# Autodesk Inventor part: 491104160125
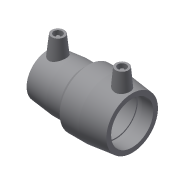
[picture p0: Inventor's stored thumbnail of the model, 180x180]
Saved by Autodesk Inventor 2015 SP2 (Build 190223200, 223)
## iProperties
Created: 2017-06
Part Number: 491104160125
Material: Generic
Description: PLASSON REDUCING COUPLER 160-125
Document SubType Name: Modeling
Designer: KIM
Mass: 54.8237 g
Surface Area: 155.252 cm^2
Volume: 54.8237 cm^3
Density: 1 g/cm^3
Appearance: Default
Author: KIM
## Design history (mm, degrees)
derived "491104.ipt"
feature "Solid1::491104.ipt"
tag "TaggingFeature1"
body "Solid1"
other parameters: "d0" = 195, "d2" = 158, "d3" = 85, "d4" = 51, "d5" = 142.2, "d7" = 125, "d8" = 168 deg, "d10" = 34, "d11" = 11.33333, "d13" = 195, "d14" = 17.6296, "d15" = 85, "d18" = 125, "d19" = 4.25, "d20" = 168 deg, "d22" = 108.92847, "d25" = 135 deg, "d29" = 89, "d30" = 15, "d31" = 68.25, "d34" = 6 deg, "d35" = 15, "d38" = 20.25, "d39" = 5 deg, "d41" = 4, "d42" = 14, "d43" = 0, "d45" = 4, "d46" = 14, "d47" = 0, "d48" = 158, "d50" = 199, "d52" = 112.5, "d53" = 37.6, "d54" = 12.53333, "d55" = 168 deg, "d56" = 56.4, "d57" = 94, "d58" = 179.1, "d59" = 4.25, "d60" = 135 deg, "d61" = 105, "d62" = 15, "d64" = 4, "d66" = 5 deg, "d67" = 14, "d68" = 0, "d69" = 68.25, "d70" = 158, "d71" = 199, "d73" = 187.06, "d76" = 4.25, "d77" = 168 deg, "d79" = 4.25, "d80" = 94, "d81" = 112.5, "d82" = 148.52, "d83" = 120 deg, "d88" = 15, "d89" = 17, "d90" = 5 deg, "d92" = 4, "d93" = 14, "d94" = 0, "d95" = 3, "d96" = 0, "d97" = 3, "d98" = 0, "d99" = 24.65, "d100" = 6.1625, "d101" = 144.0644, "d102" = 20 deg, "d103" = 27.26, "d104" = 6.815, "d105" = 181.4482, "d106" = 3.60705, "d107" = 3, "d108" = 0, "d109" = 3, "d110" = 0, "d_1" = 125, "L_" = 195, "L_2" = 85, "D_1" = 158, "A_1" = 89, "d_2" = 12, "L_1" = 94, "A_" = 105, "D_" = 199
